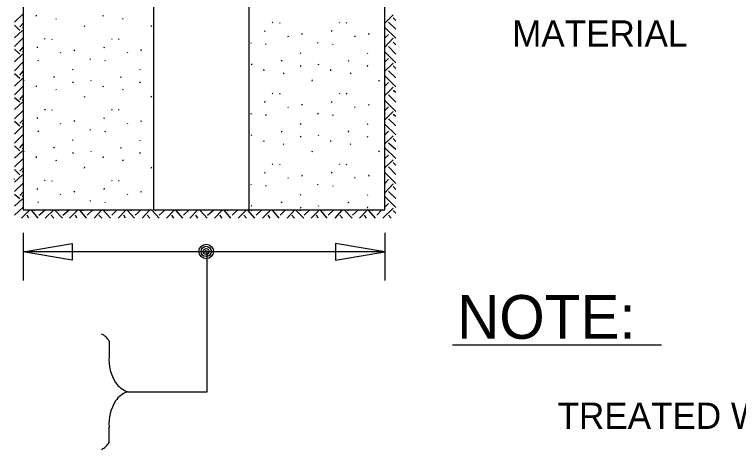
# Model space of a CAD drawing. Extents: x -2137320.7 to -2137313.2, y -2137946.3 to -2137936.1.
# Drawn here: x -2137317.499 to -2137315.842, y -2137938.081 to -2137937.087 of the extents above; entities that cross this region are included whole.
import ezdxf

# ---------------------------------------------------------------- set-up
doc = ezdxf.new("R2010")
doc.units = 0
for name, color, linetype in [('DETL-DIMS', 7, 'Continuous'), ('DETL-LINE', 7, 'Continuous'), ('DETL-NOTE', 7, 'Continuous'), ('DETL-PATT', 7, 'Continuous')]:
    doc.layers.add(name, color=color, linetype=linetype)

msp = doc.modelspace()

# ---------------------------------------------------------------- linework, layer by layer
at = {"layer": 'DETL-DIMS'}
for p, q in [((-2137317.479, -2137937.586), (-2137317.479, -2137937.695)), ((-2137316.651, -2137937.586), (-2137316.651, -2137937.695)), ((-2137316.651, -2137937.629), (-2137317.479, -2137937.629)), ((-2137317.059, -2137937.63), (-2137317.059, -2137937.95)), ((-2137317.282, -2137937.833), (-2137317.282, -2137937.87)), ((-2137317.059, -2137937.95), (-2137317.239, -2137937.95)), ((-2137317.282, -2137938.066), (-2137317.282, -2137938.03))]:
    msp.add_line(p, q, dxfattribs=at)
for points in [[(-2137317.367, -2137937.61), (-2137317.367, -2137937.648), (-2137317.479, -2137937.629)], [(-2137316.764, -2137937.61), (-2137316.764, -2137937.648), (-2137316.651, -2137937.629)]]:
    msp.add_lwpolyline(points, close=True, dxfattribs=at)
for radius in [0.0165, 0.0118, 0.00677, 0.00193]:
    msp.add_circle((-2137317.0602, -2137937.6283), radius, dxfattribs=at)
for centre, radius, start, end in [((-2137317.314, -2137937.8499), 0.0356, 27.6906, 67.1484), ((-2137317.1869, -2137937.8763), 0.0959, 175.1852, 212.6715), ((-2137317.2222, -2137937.897), 0.0551, 214.3803, 251.2502), ((-2137317.2222, -2137938.0012), 0.0551, 108.7498, 145.6197), ((-2137317.1869, -2137938.0219), 0.0959, 147.3285, 184.8148), ((-2137317.314, -2137938.0483), 0.0356, 292.8516, 332.3094)]:
    msp.add_arc(centre, radius, start, end, dxfattribs=at)
at = {"layer": 'DETL-LINE'}
for p, q in [((-2137317.479, -2137936.452), (-2137317.479, -2137937.533)), ((-2137316.651, -2137937.533), (-2137316.651, -2137936.452)), ((-2137316.962, -2137937.533), (-2137316.962, -2137936.569)), ((-2137317.181, -2137936.577), (-2137317.181, -2137937.533)), ((-2137317.479, -2137937.533), (-2137317.183, -2137937.533)), ((-2137317.181, -2137937.533), (-2137316.962, -2137937.533)), ((-2137316.962, -2137937.533), (-2137316.651, -2137937.533))]:
    msp.add_line(p, q, dxfattribs=at)
at = {"layer": 'DETL-NOTE'}
msp.add_line((-2137316.4966, -2137937.8418), (-2137316.018, -2137937.8418), dxfattribs=at)
at = {"layer": 'DETL-PATT'}
for p, q in [((-2137317.499, -2137937.104), (-2137317.479, -2137937.085)), ((-2137317.4497, -2137937.0877), (-2137317.4495, -2137937.0903)), ((-2137317.2967, -2137937.0877), (-2137317.2964, -2137937.0903)), ((-2137316.651, -2137937.106), (-2137316.632, -2137937.087)), ((-2137317.487, -2137937.115), (-2137317.479, -2137937.106)), ((-2137317.4046, -2137937.0954), (-2137317.4035, -2137937.0971)), ((-2137317.2516, -2137937.0954), (-2137317.2504, -2137937.0971)), ((-2137316.9091, -2137937.1042), (-2137316.908, -2137937.1059)), ((-2137316.8927, -2137937.1048), (-2137316.8916, -2137937.1066)), ((-2137316.7561, -2137937.1042), (-2137316.7549, -2137937.1059)), ((-2137316.7397, -2137937.1048), (-2137316.7385, -2137937.1066)), ((-2137316.626, -2137937.12), (-2137316.643, -2137937.104)), ((-2137316.626, -2137937.1), (-2137316.632, -2137937.094)), ((-2137317.487, -2137937.123), (-2137317.499, -2137937.111)), ((-2137317.499, -2137937.14), (-2137317.481, -2137937.123)), ((-2137317.479, -2137937.116), (-2137317.481, -2137937.115)), ((-2137317.3389, -2137937.1139), (-2137317.3378, -2137937.1113)), ((-2137317.1859, -2137937.1139), (-2137317.1847, -2137937.1113)), ((-2137316.9261, -2137937.1255), (-2137316.925, -2137937.1229)), ((-2137316.7731, -2137937.1255), (-2137316.7719, -2137937.1229)), ((-2137316.626, -2137937.141), (-2137316.651, -2137937.116)), ((-2137317.499, -2137937.132), (-2137317.499, -2137937.132)), ((-2137316.8734, -2137937.1355), (-2137316.8723, -2137937.1372)), ((-2137316.8412, -2137937.1321), (-2137316.8401, -2137937.1295)), ((-2137316.7204, -2137937.1355), (-2137316.7192, -2137937.1372)), ((-2137316.6882, -2137937.1321), (-2137316.687, -2137937.1295)), ((-2137316.651, -2137937.14), (-2137316.643, -2137937.132)), ((-2137317.499, -2137937.16), (-2137317.479, -2137937.14)), ((-2137317.4301, -2137937.1414), (-2137317.429, -2137937.1431)), ((-2137317.4137, -2137937.142), (-2137317.4126, -2137937.1438)), ((-2137317.2771, -2137937.1414), (-2137317.2759, -2137937.1431)), ((-2137317.2607, -2137937.142), (-2137317.2595, -2137937.1438)), ((-2137316.9583, -2137937.1505), (-2137316.9572, -2137937.1523)), ((-2137316.9243, -2137937.1537), (-2137316.9232, -2137937.1554)), ((-2137316.8053, -2137937.1505), (-2137316.8041, -2137937.1523)), ((-2137316.7713, -2137937.1537), (-2137316.7701, -2137937.1554)), ((-2137316.6522, -2137937.1505), (-2137316.6511, -2137937.1523)), ((-2137316.651, -2137937.161), (-2137316.632, -2137937.141)), ((-2137316.626, -2137937.156), (-2137316.632, -2137937.15)), ((-2137317.487, -2137937.177), (-2137317.499, -2137937.166)), ((-2137317.487, -2137937.17), (-2137317.479, -2137937.161)), ((-2137317.479, -2137937.172), (-2137317.481, -2137937.17)), ((-2137317.4471, -2137937.1627), (-2137317.4459, -2137937.1601)), ((-2137317.3944, -2137937.1727), (-2137317.3933, -2137937.1744)), ((-2137317.3622, -2137937.1693), (-2137317.3611, -2137937.1667)), ((-2137317.294, -2137937.1627), (-2137317.2929, -2137937.1601)), ((-2137317.2414, -2137937.1727), (-2137317.2402, -2137937.1744)), ((-2137317.2092, -2137937.1693), (-2137317.208, -2137937.1667)), ((-2137316.626, -2137937.197), (-2137316.651, -2137937.172)), ((-2137316.626, -2137937.177), (-2137316.643, -2137937.16)), ((-2137317.499, -2137937.195), (-2137317.481, -2137937.177)), ((-2137317.499, -2137937.187), (-2137317.499, -2137937.187)), ((-2137317.479, -2137937.1882), (-2137317.4782, -2137937.1895)), ((-2137317.3263, -2137937.1877), (-2137317.3251, -2137937.1895)), ((-2137316.8451, -2137937.1741), (-2137316.8439, -2137937.1758)), ((-2137316.692, -2137937.1741), (-2137316.6909, -2137937.1758)), ((-2137316.651, -2137937.195), (-2137316.643, -2137937.187)), ((-2137317.499, -2137937.215), (-2137317.479, -2137937.195)), ((-2137317.4453, -2137937.1908), (-2137317.4442, -2137937.1926)), ((-2137317.2923, -2137937.1908), (-2137317.2911, -2137937.1926)), ((-2137316.9573, -2137937.1996), (-2137316.9561, -2137937.2014)), ((-2137316.8879, -2137937.1934), (-2137316.8867, -2137937.1908)), ((-2137316.8441, -2137937.2052), (-2137316.843, -2137937.2026)), ((-2137316.8042, -2137937.1996), (-2137316.803, -2137937.2014)), ((-2137316.7348, -2137937.1934), (-2137316.7336, -2137937.1908)), ((-2137316.6911, -2137937.2052), (-2137316.6899, -2137937.2026)), ((-2137316.651, -2137937.216), (-2137316.632, -2137937.198)), ((-2137316.626, -2137937.21), (-2137316.632, -2137937.204)), ((-2137317.487, -2137937.233), (-2137317.499, -2137937.222)), ((-2137317.487, -2137937.225), (-2137317.479, -2137937.216)), ((-2137317.366, -2137937.2113), (-2137317.3649, -2137937.213)), ((-2137317.213, -2137937.2113), (-2137317.2118, -2137937.213)), ((-2137316.9288, -2137937.2124), (-2137316.9285, -2137937.215)), ((-2137316.8837, -2137937.2201), (-2137316.8825, -2137937.2218)), ((-2137316.7757, -2137937.2124), (-2137316.7754, -2137937.215)), ((-2137316.7306, -2137937.2201), (-2137316.7295, -2137937.2218)), ((-2137316.626, -2137937.231), (-2137316.643, -2137937.215)), ((-2137317.499, -2137937.25), (-2137317.481, -2137937.233)), ((-2137317.479, -2137937.227), (-2137317.481, -2137937.225)), ((-2137317.4782, -2137937.2368), (-2137317.4771, -2137937.2385)), ((-2137317.4088, -2137937.2306), (-2137317.4077, -2137937.228)), ((-2137317.3252, -2137937.2368), (-2137317.324, -2137937.2385)), ((-2137317.2558, -2137937.2306), (-2137317.2546, -2137937.228)), ((-2137316.8179, -2137937.2386), (-2137316.8168, -2137937.236)), ((-2137316.6649, -2137937.2386), (-2137316.6637, -2137937.236)), ((-2137316.626, -2137937.252), (-2137316.651, -2137937.227)), ((-2137317.499, -2137937.242), (-2137317.499, -2137937.242)), ((-2137317.499, -2137937.27), (-2137317.479, -2137937.25)), ((-2137317.4497, -2137937.2496), (-2137317.4495, -2137937.2522)), ((-2137317.3651, -2137937.2424), (-2137317.3639, -2137937.2398)), ((-2137317.2967, -2137937.2496), (-2137317.2964, -2137937.2522)), ((-2137317.212, -2137937.2424), (-2137317.2109, -2137937.2398)), ((-2137316.651, -2137937.25), (-2137316.643, -2137937.242)), ((-2137316.651, -2137937.272), (-2137316.632, -2137937.253)), ((-2137317.487, -2137937.281), (-2137317.479, -2137937.272)), ((-2137317.4046, -2137937.2573), (-2137317.4035, -2137937.259)), ((-2137317.2516, -2137937.2573), (-2137317.2504, -2137937.259)), ((-2137316.9091, -2137937.2661), (-2137316.908, -2137937.2678)), ((-2137316.8927, -2137937.2667), (-2137316.8916, -2137937.2685)), ((-2137316.7561, -2137937.2661), (-2137316.7549, -2137937.2678)), ((-2137316.7397, -2137937.2667), (-2137316.7385, -2137937.2685)), ((-2137316.626, -2137937.287), (-2137316.643, -2137937.27)), ((-2137316.626, -2137937.265), (-2137316.632, -2137937.26)), ((-2137317.487, -2137937.287), (-2137317.499, -2137937.277)), ((-2137317.499, -2137937.304), (-2137317.481, -2137937.287)), ((-2137317.479, -2137937.283), (-2137317.481, -2137937.281)), ((-2137317.3389, -2137937.2758), (-2137317.3378, -2137937.2732)), ((-2137317.1859, -2137937.2758), (-2137317.1847, -2137937.2732)), ((-2137316.9261, -2137937.2874), (-2137316.925, -2137937.2848)), ((-2137316.7731, -2137937.2874), (-2137316.7719, -2137937.2848)), ((-2137316.626, -2137937.308), (-2137316.651, -2137937.283)), ((-2137317.499, -2137937.298), (-2137317.499, -2137937.298)), ((-2137317.4301, -2137937.3033), (-2137317.429, -2137937.305)), ((-2137317.4137, -2137937.3039), (-2137317.4126, -2137937.3056)), ((-2137317.2771, -2137937.3033), (-2137317.2759, -2137937.305)), ((-2137317.2607, -2137937.3039), (-2137317.2595, -2137937.3056)), ((-2137316.8734, -2137937.2974), (-2137316.8723, -2137937.2991)), ((-2137316.8412, -2137937.294), (-2137316.8401, -2137937.2914)), ((-2137316.7204, -2137937.2974), (-2137316.7192, -2137937.2991)), ((-2137316.6882, -2137937.294), (-2137316.687, -2137937.2914)), ((-2137316.651, -2137937.306), (-2137316.643, -2137937.298)), ((-2137317.499, -2137937.325), (-2137317.479, -2137937.306)), ((-2137317.4471, -2137937.3246), (-2137317.4459, -2137937.322)), ((-2137317.294, -2137937.3246), (-2137317.2929, -2137937.322)), ((-2137316.9583, -2137937.3124), (-2137316.9572, -2137937.3142)), ((-2137316.9243, -2137937.3155), (-2137316.9232, -2137937.3173)), ((-2137316.8053, -2137937.3124), (-2137316.8041, -2137937.3142)), ((-2137316.7713, -2137937.3155), (-2137316.7701, -2137937.3173)), ((-2137316.6522, -2137937.3124), (-2137316.6511, -2137937.3142)), ((-2137316.651, -2137937.327), (-2137316.632, -2137937.308)), ((-2137316.626, -2137937.32), (-2137316.632, -2137937.315)), ((-2137317.487, -2137937.342), (-2137317.499, -2137937.331)), ((-2137317.487, -2137937.335), (-2137317.479, -2137937.327)), ((-2137317.479, -2137937.337), (-2137317.481, -2137937.335)), ((-2137317.3944, -2137937.3346), (-2137317.3933, -2137937.3363)), ((-2137317.3622, -2137937.3312), (-2137317.3611, -2137937.3286)), ((-2137317.2414, -2137937.3346), (-2137317.2402, -2137937.3363)), ((-2137317.2092, -2137937.3312), (-2137317.208, -2137937.3286)), ((-2137316.8451, -2137937.336), (-2137316.8439, -2137937.3377)), ((-2137316.692, -2137937.336), (-2137316.6909, -2137937.3377)), ((-2137316.626, -2137937.362), (-2137316.651, -2137937.337)), ((-2137316.626, -2137937.341), (-2137316.643, -2137937.325)), ((-2137317.499, -2137937.36), (-2137317.481, -2137937.342)), ((-2137317.499, -2137937.353), (-2137317.499, -2137937.353)), ((-2137317.479, -2137937.3501), (-2137317.4782, -2137937.3513)), ((-2137317.4453, -2137937.3527), (-2137317.4442, -2137937.3545)), ((-2137317.3263, -2137937.3496), (-2137317.3251, -2137937.3513)), ((-2137317.2923, -2137937.3527), (-2137317.2911, -2137937.3545)), ((-2137316.8879, -2137937.3553), (-2137316.8867, -2137937.3527)), ((-2137316.7348, -2137937.3553), (-2137316.7336, -2137937.3527)), ((-2137316.651, -2137937.362), (-2137316.643, -2137937.353)), ((-2137317.499, -2137937.381), (-2137317.479, -2137937.361)), ((-2137316.9573, -2137937.3615), (-2137316.9561, -2137937.3632)), ((-2137316.8441, -2137937.3671), (-2137316.843, -2137937.3645)), ((-2137316.8042, -2137937.3615), (-2137316.803, -2137937.3632)), ((-2137316.6911, -2137937.3671), (-2137316.6899, -2137937.3645)), ((-2137316.651, -2137937.382), (-2137316.632, -2137937.364)), ((-2137316.626, -2137937.377), (-2137316.632, -2137937.37)), ((-2137317.487, -2137937.398), (-2137317.499, -2137937.387)), ((-2137317.487, -2137937.391), (-2137317.479, -2137937.382)), ((-2137317.366, -2137937.3732), (-2137317.3649, -2137937.3749)), ((-2137317.213, -2137937.3732), (-2137317.2118, -2137937.3749)), ((-2137316.9288, -2137937.3743), (-2137316.9285, -2137937.3769)), ((-2137316.8837, -2137937.382), (-2137316.8825, -2137937.3837)), ((-2137316.7757, -2137937.3743), (-2137316.7754, -2137937.3769)), ((-2137316.7306, -2137937.382), (-2137316.7295, -2137937.3837)), ((-2137316.626, -2137937.395), (-2137316.643, -2137937.381)), ((-2137317.499, -2137937.415), (-2137317.481, -2137937.398)), ((-2137317.479, -2137937.394), (-2137317.481, -2137937.391)), ((-2137317.4782, -2137937.3987), (-2137317.4771, -2137937.4004)), ((-2137317.4088, -2137937.3925), (-2137317.4077, -2137937.3899)), ((-2137317.3651, -2137937.4043), (-2137317.3639, -2137937.4017)), ((-2137317.3252, -2137937.3987), (-2137317.324, -2137937.4004)), ((-2137317.2558, -2137937.3925), (-2137317.2546, -2137937.3899)), ((-2137317.212, -2137937.4043), (-2137317.2109, -2137937.4017)), ((-2137316.8179, -2137937.4005), (-2137316.8168, -2137937.3979)), ((-2137316.6649, -2137937.4005), (-2137316.6637, -2137937.3979)), ((-2137316.626, -2137937.416), (-2137316.651, -2137937.391)), ((-2137317.499, -2137937.408), (-2137317.499, -2137937.408)), ((-2137317.499, -2137937.435), (-2137317.479, -2137937.416)), ((-2137317.4497, -2137937.4115), (-2137317.4495, -2137937.4141)), ((-2137317.4046, -2137937.4191), (-2137317.4035, -2137937.4209)), ((-2137317.2967, -2137937.4115), (-2137317.2964, -2137937.4141)), ((-2137317.2516, -2137937.4191), (-2137317.2504, -2137937.4209)), ((-2137316.651, -2137937.416), (-2137316.643, -2137937.408)), ((-2137316.651, -2137937.437), (-2137316.632, -2137937.419)), ((-2137317.487, -2137937.445), (-2137317.479, -2137937.437)), ((-2137317.3389, -2137937.4377), (-2137317.3378, -2137937.4351)), ((-2137317.1859, -2137937.4377), (-2137317.1847, -2137937.4351)), ((-2137316.9091, -2137937.428), (-2137316.908, -2137937.4297)), ((-2137316.8927, -2137937.4286), (-2137316.8916, -2137937.4303)), ((-2137316.7561, -2137937.428), (-2137316.7549, -2137937.4297)), ((-2137316.7397, -2137937.4286), (-2137316.7385, -2137937.4303)), ((-2137316.626, -2137937.452), (-2137316.643, -2137937.435)), ((-2137316.626, -2137937.431), (-2137316.632, -2137937.425)), ((-2137317.487, -2137937.453), (-2137317.499, -2137937.441)), ((-2137317.499, -2137937.47), (-2137317.481, -2137937.453)), ((-2137317.479, -2137937.448), (-2137317.481, -2137937.445)), ((-2137316.9261, -2137937.4493), (-2137316.925, -2137937.4467)), ((-2137316.8412, -2137937.4559), (-2137316.8401, -2137937.4533)), ((-2137316.7731, -2137937.4493), (-2137316.7719, -2137937.4467)), ((-2137316.6882, -2137937.4559), (-2137316.687, -2137937.4533)), ((-2137316.626, -2137937.473), (-2137316.651, -2137937.448)), ((-2137317.499, -2137937.464), (-2137317.499, -2137937.462)), ((-2137317.4301, -2137937.4651), (-2137317.429, -2137937.4669)), ((-2137317.4137, -2137937.4658), (-2137317.4126, -2137937.4675)), ((-2137317.2771, -2137937.4651), (-2137317.2759, -2137937.4669)), ((-2137317.2607, -2137937.4658), (-2137317.2595, -2137937.4675)), ((-2137316.8734, -2137937.4593), (-2137316.8723, -2137937.461)), ((-2137316.7204, -2137937.4593), (-2137316.7192, -2137937.461)), ((-2137316.651, -2137937.473), (-2137316.643, -2137937.464)), ((-2137317.499, -2137937.491), (-2137317.479, -2137937.472)), ((-2137317.4471, -2137937.4865), (-2137317.4459, -2137937.4839)), ((-2137317.294, -2137937.4865), (-2137317.2929, -2137937.4839)), ((-2137316.9583, -2137937.4743), (-2137316.9572, -2137937.476)), ((-2137316.9243, -2137937.4774), (-2137316.9232, -2137937.4792)), ((-2137316.8053, -2137937.4743), (-2137316.8041, -2137937.476)), ((-2137316.7713, -2137937.4774), (-2137316.7701, -2137937.4792)), ((-2137316.6522, -2137937.4743), (-2137316.6511, -2137937.476)), ((-2137316.651, -2137937.494), (-2137316.632, -2137937.474)), ((-2137316.626, -2137937.487), (-2137316.632, -2137937.48)), ((-2137317.487, -2137937.508), (-2137317.499, -2137937.498)), ((-2137317.487, -2137937.5), (-2137317.479, -2137937.492)), ((-2137317.479, -2137937.504), (-2137317.481, -2137937.5)), ((-2137317.3944, -2137937.4965), (-2137317.3933, -2137937.4982)), ((-2137317.3622, -2137937.4931), (-2137317.3611, -2137937.4905)), ((-2137317.2414, -2137937.4965), (-2137317.2402, -2137937.4982)), ((-2137317.2092, -2137937.4931), (-2137317.208, -2137937.4905)), ((-2137316.8451, -2137937.4979), (-2137316.8439, -2137937.4996)), ((-2137316.692, -2137937.4979), (-2137316.6909, -2137937.4996)), ((-2137316.626, -2137937.528), (-2137316.651, -2137937.503)), ((-2137316.626, -2137937.507), (-2137316.643, -2137937.491)), ((-2137317.499, -2137937.525), (-2137317.481, -2137937.508)), ((-2137317.499, -2137937.519), (-2137317.499, -2137937.519)), ((-2137317.479, -2137937.512), (-2137317.4782, -2137937.5132)), ((-2137317.4453, -2137937.5146), (-2137317.4442, -2137937.5163)), ((-2137317.3263, -2137937.5115), (-2137317.3251, -2137937.5132)), ((-2137317.2923, -2137937.5146), (-2137317.2911, -2137937.5163)), ((-2137316.8879, -2137937.5172), (-2137316.8867, -2137937.5146)), ((-2137316.7348, -2137937.5172), (-2137316.7336, -2137937.5146)), ((-2137316.651, -2137937.527), (-2137316.643, -2137937.519)), ((-2137317.499, -2137937.545), (-2137317.479, -2137937.527)), ((-2137317.483, -2137937.552), (-2137317.464, -2137937.533)), ((-2137317.445, -2137937.552), (-2137317.459, -2137937.535)), ((-2137317.454, -2137937.535), (-2137317.451, -2137937.533)), ((-2137317.443, -2137937.545), (-2137317.429, -2137937.533)), ((-2137317.429, -2137937.552), (-2137317.409, -2137937.533)), ((-2137317.389, -2137937.552), (-2137317.406, -2137937.535)), ((-2137317.399, -2137937.535), (-2137317.395, -2137937.533)), ((-2137317.388, -2137937.545), (-2137317.374, -2137937.533)), ((-2137317.373, -2137937.552), (-2137317.354, -2137937.533)), ((-2137317.334, -2137937.552), (-2137317.349, -2137937.535)), ((-2137317.343, -2137937.535), (-2137317.34, -2137937.533)), ((-2137317.333, -2137937.545), (-2137317.32, -2137937.533)), ((-2137317.317, -2137937.552), (-2137317.299, -2137937.533)), ((-2137317.279, -2137937.552), (-2137317.295, -2137937.535)), ((-2137317.288, -2137937.535), (-2137317.284, -2137937.533)), ((-2137317.276, -2137937.545), (-2137317.264, -2137937.533)), ((-2137317.262, -2137937.552), (-2137317.243, -2137937.533)), ((-2137317.224, -2137937.552), (-2137317.24, -2137937.535)), ((-2137317.233, -2137937.535), (-2137317.229, -2137937.533)), ((-2137317.223, -2137937.545), (-2137317.209, -2137937.533)), ((-2137317.207, -2137937.552), (-2137317.189, -2137937.533)), ((-2137317.168, -2137937.552), (-2137317.184, -2137937.535)), ((-2137317.178, -2137937.535), (-2137317.174, -2137937.533)), ((-2137317.168, -2137937.545), (-2137317.154, -2137937.533)), ((-2137317.151, -2137937.552), (-2137317.133, -2137937.533)), ((-2137317.114, -2137937.552), (-2137317.129, -2137937.535)), ((-2137317.123, -2137937.535), (-2137317.119, -2137937.533)), ((-2137317.112, -2137937.545), (-2137317.099, -2137937.533)), ((-2137317.098, -2137937.552), (-2137317.079, -2137937.533)), ((-2137317.058, -2137937.552), (-2137317.074, -2137937.535)), ((-2137317.066, -2137937.535), (-2137317.064, -2137937.533)), ((-2137317.057, -2137937.545), (-2137317.043, -2137937.533)), ((-2137317.041, -2137937.552), (-2137317.023, -2137937.533)), ((-2137317.004, -2137937.552), (-2137317.018, -2137937.535)), ((-2137317.012, -2137937.535), (-2137317.009, -2137937.533)), ((-2137317.001, -2137937.545), (-2137316.988, -2137937.533)), ((-2137316.987, -2137937.552), (-2137316.968, -2137937.533)), ((-2137316.949, -2137937.552), (-2137316.964, -2137937.535)), ((-2137316.9573, -2137937.5234), (-2137316.9561, -2137937.5251)), ((-2137316.957, -2137937.535), (-2137316.954, -2137937.533)), ((-2137316.946, -2137937.545), (-2137316.933, -2137937.533)), ((-2137316.931, -2137937.552), (-2137316.912, -2137937.533)), ((-2137316.893, -2137937.552), (-2137316.908, -2137937.535)), ((-2137316.901, -2137937.535), (-2137316.899, -2137937.533)), ((-2137316.891, -2137937.545), (-2137316.879, -2137937.533)), ((-2137316.875, -2137937.552), (-2137316.857, -2137937.533)), ((-2137316.837, -2137937.552), (-2137316.854, -2137937.535)), ((-2137316.846, -2137937.535), (-2137316.843, -2137937.533)), ((-2137316.8441, -2137937.529), (-2137316.843, -2137937.5264)), ((-2137316.836, -2137937.545), (-2137316.823, -2137937.533)), ((-2137316.82, -2137937.552), (-2137316.801, -2137937.533)), ((-2137316.8042, -2137937.5234), (-2137316.803, -2137937.5251)), ((-2137316.783, -2137937.552), (-2137316.798, -2137937.535)), ((-2137316.791, -2137937.535), (-2137316.788, -2137937.533)), ((-2137316.781, -2137937.545), (-2137316.768, -2137937.533)), ((-2137316.765, -2137937.552), (-2137316.748, -2137937.533)), ((-2137316.726, -2137937.552), (-2137316.743, -2137937.535)), ((-2137316.736, -2137937.535), (-2137316.733, -2137937.533)), ((-2137316.725, -2137937.545), (-2137316.712, -2137937.533)), ((-2137316.709, -2137937.552), (-2137316.691, -2137937.533)), ((-2137316.6911, -2137937.529), (-2137316.6899, -2137937.5264)), ((-2137316.673, -2137937.552), (-2137316.688, -2137937.535)), ((-2137316.681, -2137937.535), (-2137316.678, -2137937.533)), ((-2137316.67, -2137937.545), (-2137316.658, -2137937.533)), ((-2137316.656, -2137937.552), (-2137316.632, -2137937.529)), ((-2137316.626, -2137937.541), (-2137316.632, -2137937.535)), ((-2137317.466, -2137937.552), (-2137317.47, -2137937.545)), ((-2137317.409, -2137937.552), (-2137317.415, -2137937.545)), ((-2137317.356, -2137937.552), (-2137317.359, -2137937.545)), ((-2137317.299, -2137937.552), (-2137317.306, -2137937.545)), ((-2137317.245, -2137937.552), (-2137317.249, -2137937.545)), ((-2137317.189, -2137937.552), (-2137317.195, -2137937.545)), ((-2137317.134, -2137937.552), (-2137317.139, -2137937.545)), ((-2137317.079, -2137937.552), (-2137317.084, -2137937.545)), ((-2137317.024, -2137937.552), (-2137317.029, -2137937.545)), ((-2137316.968, -2137937.552), (-2137316.974, -2137937.545)), ((-2137316.914, -2137937.552), (-2137316.918, -2137937.545)), ((-2137316.858, -2137937.552), (-2137316.864, -2137937.545)), ((-2137316.804, -2137937.552), (-2137316.808, -2137937.545)), ((-2137316.748, -2137937.552), (-2137316.754, -2137937.545)), ((-2137316.693, -2137937.552), (-2137316.698, -2137937.545)), ((-2137316.637, -2137937.552), (-2137316.643, -2137937.545))]:
    msp.add_line(p, q, dxfattribs=at)

# ---------------------------------------------------------------- texts
at = {"layer": 'DETL-NOTE'}
for s, height, p in [('MATERIAL', 0.06, (-2137316.36, -2137937.16)), ('NOTE:', 0.1, (-2137316.486, -2137937.828)), ('TREATED WOODEN POST SHALL BE PLACED IN', 0.06, (-2137316.256, -2137938.034))]:
    msp.add_text(s, height=height, dxfattribs=at).set_placement(p)

doc.saveas('drawing.dxf')
